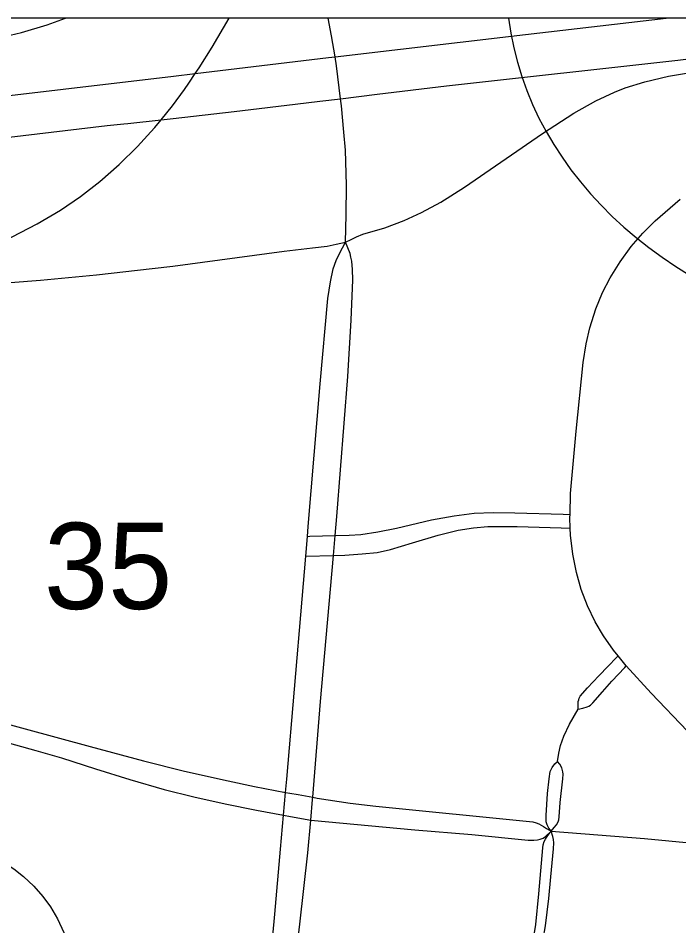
# Model space of a CAD drawing. Extents: x 0 to 34, y 0 to 22.
# Drawn here: x 6.3873 to 6.7082, y 20.6652 to 21.1059 of the extents above; entities that cross this region are included whole.
import ezdxf

# ---------------------------------------------------------------- set-up
doc = ezdxf.new("R2010")
doc.units = 0
for name, color, linetype in [('Default', 7, 'Continuous'), ('GM_X_City_Street', 7, 'Continuous'), ('GM_X_Corporation', 7, 'Continuous'), ('GM_X_County_Road', 7, 'Continuous'), ('GM_X_Interchange_Ramps', 7, 'Continuous'), ('GM_X_Interstate_Route', 7, 'Continuous'), ('GM_X_Section_Text', 7, 'Continuous'), ('GM_X_State_Route', 7, 'Continuous')]:
    doc.layers.add(name, color=color, linetype=linetype)

msp = doc.modelspace()

# ---------------------------------------------------------------- linework, layer by layer
at = {"layer": 'Default'}
msp.add_line((6.97842, 21.10587), (6.62546, 21.10587), dxfattribs=at)
msp.add_ellipse((6.84633, 21.12332), major_axis=(0.22195, 0), ratio=0.8, start_param=3.240014, end_param=4.511031, dxfattribs=at)
at = {"layer": 'GM_X_City_Street'}
for points in [[(6.71235, 20.75972), (6.69475, 20.77817), (6.68265, 20.79143), (6.67866, 20.79625), (6.67641, 20.79899), (6.67152, 20.806), (6.6675, 20.81284), (6.66381, 20.82054), (6.66079, 20.82852), (6.65843, 20.83674), (6.65664, 20.84573), (6.65555, 20.85483), (6.65544, 20.85822), (6.65526, 20.86338), (6.65531, 20.86494), (6.65562, 20.87507), (6.65825, 20.90535), (6.66169, 20.93868), (6.66308, 20.94777), (6.66493, 20.95548), (6.66791, 20.96481), (6.67116, 20.9727), (6.6748, 20.97974), (6.67966, 20.98753), (6.68506, 20.99495), (6.69061, 21.00145), (6.69667, 21.00749), (6.70879, 21.01801)], [(6.52778, 20.85429), (6.52893, 20.85433), (6.54125, 20.85469), (6.54809, 20.85488), (6.55369, 20.85515), (6.56195, 20.85642), (6.57112, 20.85833), (6.58803, 20.86234), (6.59899, 20.86425), (6.60879, 20.8655), (6.61802, 20.86596), (6.62852, 20.86579), (6.65191, 20.86504), (6.65531, 20.86494)], [(6.52696, 20.84461), (6.54043, 20.84506), (6.54593, 20.84524), (6.55444, 20.84574), (6.56159, 20.8465), (6.5682, 20.84787), (6.57882, 20.85112), (6.59133, 20.85493), (6.60106, 20.8573), (6.60849, 20.85848), (6.61537, 20.85902), (6.62959, 20.85914), (6.65096, 20.85838), (6.65544, 20.85822)], [(6.6592, 20.77047), (6.65925, 20.77299), (6.65934, 20.77407), (6.65952, 20.7749), (6.65981, 20.77573), (6.66022, 20.77665), (6.66376, 20.7808), (6.66929, 20.78665), (6.67383, 20.79134), (6.67789, 20.79546), (6.67866, 20.79625)], [(6.6592, 20.77047), (6.66148, 20.77085), (6.66361, 20.77146), (6.66447, 20.77186), (6.6653, 20.77242), (6.66637, 20.77344), (6.6711, 20.77887), (6.67561, 20.78399), (6.68196, 20.7907), (6.68265, 20.79143)], [(6.6493, 20.74496), (6.64989, 20.749), (6.65074, 20.75283), (6.65226, 20.75722), (6.65498, 20.7632), (6.6592, 20.77047)], [(6.63772, 20.65983), (6.63877, 20.66594), (6.64013, 20.68078), (6.64204, 20.70305), (6.64226, 20.70456), (6.64277, 20.70609), (6.6434, 20.70733), (6.64425, 20.70853), (6.64612, 20.71119), (6.6451, 20.71261), (6.64425, 20.7142), (6.64379, 20.71567), (6.64368, 20.71749), (6.64374, 20.71874), (6.64442, 20.72953), (6.64516, 20.73666), (6.64569, 20.74011), (6.6466, 20.74207), (6.64798, 20.7438), (6.6493, 20.74496)], [(6.64227, 20.65881), (6.64345, 20.66528), (6.64498, 20.67846), (6.64601, 20.68908), (6.64732, 20.70265), (6.64742, 20.70558), (6.64725, 20.70717), (6.64691, 20.70864), (6.64612, 20.71119), (6.64765, 20.71295), (6.64867, 20.71431), (6.64952, 20.71567), (6.64981, 20.71664), (6.65003, 20.71811), (6.65058, 20.72507), (6.65174, 20.73651), (6.6519, 20.73884), (6.6518, 20.74002), (6.6513, 20.74188), (6.65039, 20.74373), (6.6493, 20.74496)], [(6.32296, 20.71422), (6.34106, 20.70956), (6.35788, 20.70522), (6.36615, 20.70271), (6.37244, 20.70028), (6.37846, 20.69726), (6.38514, 20.6929), (6.38995, 20.6891), (6.39486, 20.68447), (6.39933, 20.67942), (6.40294, 20.67448), (6.40637, 20.66868), (6.40946, 20.662), (6.41242, 20.65388), (6.42536, 20.61368), (6.42937, 20.60127)]]:
    msp.add_lwpolyline(points, dxfattribs=at)
at = {"layer": 'GM_X_Corporation'}
for points in [[(8.71189, 14.30587), (8.71189, 21.10587), (4.05187, 21.10587)], [(8.71189, 14.30587), (8.71189, 21.02216), (8.61486, 21.03591), (8.24427, 21.07383), (8.1735, 21.08097), (8.1315, 21.08535), (8.11104, 21.08726), (7.91119, 21.10587), (4.05187, 21.10587)]]:
    msp.add_lwpolyline(points, dxfattribs=at)
msp.add_lwpolyline([(7.06384, 21.10587), (6.05195, 21.10587), (5.98271, 20.25288), (6.97134, 20.15852)], close=True, dxfattribs=at)
at = {"layer": 'GM_X_County_Road'}
msp.add_line((6.54043, 20.84506), (6.54125, 20.85469), dxfattribs=at)
for points in [[(6.54547, 21.05053), (6.54432, 21.06324), (6.54389, 21.06677), (6.54193, 21.0828), (6.54123, 21.08708), (6.53954, 21.09734), (6.5378, 21.10587)], [(6.54623, 20.99718), (6.54665, 21.01031), (6.54683, 21.02472), (6.54627, 21.04174), (6.54547, 21.05053)], [(6.50723, 20.62014), (6.51198, 20.67088), (6.5147, 20.70246), (6.51616, 20.7189), (6.51715, 20.72998), (6.51773, 20.73649), (6.52519, 20.82376), (6.52696, 20.84461), (6.52778, 20.85429), (6.52818, 20.85905), (6.53396, 20.92839), (6.5377, 20.96979), (6.53895, 20.97781), (6.54031, 20.9842), (6.54176, 20.98826), (6.5433, 20.99154), (6.54623, 20.99718)], [(6.54125, 20.85469), (6.54204, 20.86389), (6.54748, 20.93197), (6.549, 20.95921), (6.54982, 20.9789), (6.54973, 20.9838), (6.54928, 20.98788), (6.54889, 20.98984), (6.54847, 20.99154), (6.54623, 20.99718)], [(6.52939, 20.71659), (6.53029, 20.72653), (6.53039, 20.72765), (6.53415, 20.7742), (6.53902, 20.82863), (6.54043, 20.84506)], [(6.334, 20.77239), (6.33729, 20.77308), (6.33995, 20.77322), (6.34226, 20.77322), (6.34464, 20.77301), (6.34702, 20.7726), (6.37382, 20.76543), (6.42236, 20.75229), (6.44815, 20.74536), (6.46804, 20.74037), (6.48925, 20.73557), (6.50203, 20.7329), (6.51715, 20.72998), (6.51918, 20.72967)], [(6.334, 20.77239), (6.33568, 20.77071), (6.33645, 20.76994), (6.33729, 20.76896), (6.33834, 20.76776), (6.33946, 20.76686), (6.34065, 20.76602), (6.34219, 20.76525), (6.34562, 20.76413), (6.35745, 20.76091), (6.373, 20.75661), (6.39582, 20.75042), (6.40836, 20.74672), (6.42493, 20.74138), (6.44153, 20.73621), (6.45825, 20.73148), (6.47269, 20.72783), (6.48783, 20.72447), (6.50306, 20.72143), (6.51616, 20.7189)], [(6.51918, 20.72967), (6.52322, 20.72905), (6.53039, 20.72765), (6.53259, 20.72727), (6.54857, 20.72481), (6.56093, 20.72334), (6.63721, 20.71567), (6.63886, 20.71528), (6.64011, 20.71477), (6.6413, 20.71414), (6.64238, 20.71346), (6.6439, 20.7125), (6.64612, 20.71119)], [(6.51616, 20.7189), (6.51961, 20.71823), (6.52939, 20.71659), (6.57995, 20.71185), (6.60768, 20.7095), (6.635, 20.70677), (6.63772, 20.70677), (6.63959, 20.70699), (6.64079, 20.70728), (6.6422, 20.70779), (6.64345, 20.70864), (6.64612, 20.71119)], [(6.52013, 20.63143), (6.52414, 20.66604), (6.52794, 20.70059), (6.52939, 20.71659)], [(6.64612, 20.71119), (6.6915, 20.70764), (6.71503, 20.70531), (6.73854, 20.70311), (6.76265, 20.70088), (6.7948, 20.69793), (6.8189, 20.69565), (6.84241, 20.69344), (6.86593, 20.69133), (6.8794, 20.69008)]]:
    msp.add_lwpolyline(points, dxfattribs=at)
at = {"layer": 'GM_X_Interchange_Ramps'}
for points in [[(6.54623, 20.99718), (6.54903, 20.99848), (6.55155, 20.99963), (6.55471, 21.00093), (6.56543, 21.00413), (6.57475, 21.00763), (6.58325, 21.01147), (6.59251, 21.01655), (6.60403, 21.0239), (6.64194, 21.0499), (6.65709, 21.05967), (6.66791, 21.06578), (6.67692, 21.06997), (6.68213, 21.072), (6.6916, 21.07502), (6.70309, 21.07773), (6.71964, 21.08049), (6.7628, 21.08633), (6.77393, 21.0879)], [(6.4524, 20.98434), (6.46241, 20.9855), (6.51657, 20.99277), (6.53032, 20.9943), (6.53736, 20.9952), (6.54169, 20.9961), (6.54623, 20.99718)], [(6.25304, 20.9777), (6.26962, 20.97572), (6.28547, 20.97471), (6.29593, 20.97445), (6.30601, 20.97429), (6.34487, 20.9752), (6.37092, 20.97654), (6.39818, 20.97859), (6.42539, 20.98123), (6.4524, 20.98434)]]:
    msp.add_lwpolyline(points, dxfattribs=at)
at = {"layer": 'GM_X_Interstate_Route'}
msp.add_line((6.43858, 21.05456), (6.4406, 21.05478), dxfattribs=at)
for points in [[(6.35542, 21.06506), (6.46279, 21.07777), (6.47334, 21.07903), (6.53807, 21.08671), (6.54123, 21.08708), (6.63371, 21.09798), (6.70194, 21.10587)], [(6.56168, 21.06891), (6.59529, 21.07295), (6.70767, 21.08546), (6.77414, 21.09378)], [(6.53388, 21.06556), (6.54389, 21.06677), (6.56168, 21.06891)], [(6.49621, 21.06108), (6.52187, 21.06411), (6.53388, 21.06556)], [(6.4406, 21.05478), (6.4567, 21.05653), (6.46265, 21.05717), (6.49227, 21.06061), (6.49621, 21.06108)], [(6.3753, 21.04719), (6.38301, 21.04811), (6.43053, 21.05369), (6.43858, 21.05456)]]:
    msp.add_lwpolyline(points, dxfattribs=at)
at = {"layer": 'GM_X_State_Route'}
for points in [[(5.76854, 20.99652), (5.77837, 21.00024), (5.78581, 21.0025), (5.79421, 21.0046), (5.80566, 21.00628), (5.8288, 21.00926), (5.89289, 21.01754), (6.00192, 21.03221), (6.06287, 21.04071), (6.0985, 21.0462), (6.1377, 21.05307), (6.22237, 21.06841), (6.23064, 21.0699), (6.25631, 21.07458), (6.30702, 21.0837), (6.35846, 21.09244), (6.37496, 21.09562), (6.38891, 21.09894), (6.40146, 21.10267), (6.41032, 21.10587)], [(6.47017, 21.07431), (6.47334, 21.07903), (6.47521, 21.08181), (6.48159, 21.09184), (6.48979, 21.10587)], [(6.45169, 21.05064), (6.45362, 21.05277), (6.4567, 21.05653), (6.46231, 21.06336), (6.46806, 21.07117), (6.47017, 21.07431)], [(6.27081, 20.97792), (6.28167, 20.97806), (6.29909, 20.9784), (6.31152, 20.97923), (6.32266, 20.98062), (6.33553, 20.983), (6.34823, 20.98616), (6.36073, 20.99002), (6.3724, 20.99442), (6.38435, 20.99975), (6.39654, 21.00603), (6.40781, 21.01268), (6.41761, 21.01934), (6.42698, 21.02659), (6.43637, 21.0348), (6.44528, 21.04352), (6.45169, 21.05064)]]:
    msp.add_lwpolyline(points, dxfattribs=at)

# ---------------------------------------------------------------- texts
at = {"layer": 'GM_X_Section_Text'}
msp.add_text('35', height=0.041856, rotation=0, dxfattribs=at).set_placement((6.39989, 20.81904))

doc.saveas('drawing.dxf')
